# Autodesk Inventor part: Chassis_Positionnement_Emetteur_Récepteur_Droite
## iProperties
Created: 2008-12
Part Number: Chassis_Positionnement_Emetteur_Récepteur_Droite
Document SubType Name: Sheet Metal
Designer: claivier
Author: claivier
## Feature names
1. Corps dérivé1 [Tagging]
